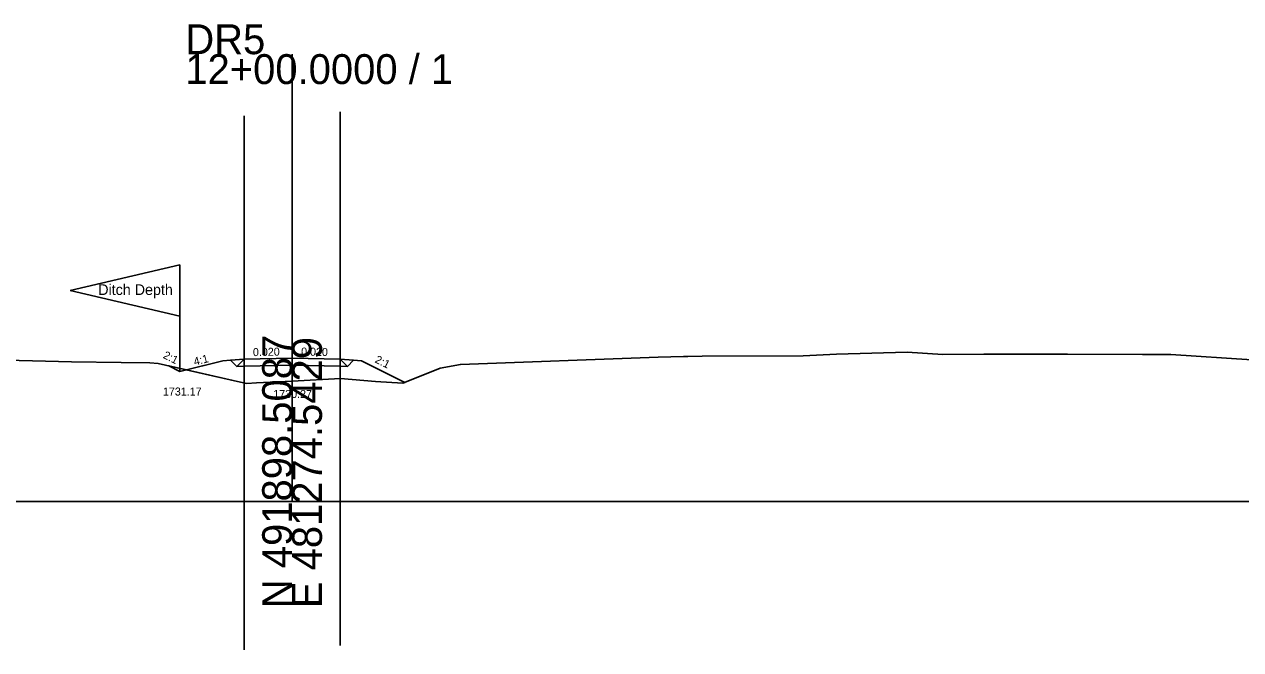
# Model space of a CAD drawing. Extents: x -26 to 403, y -10 to 2534.
# Drawn here: x 174.9 to 288.9, y 1986.1 to 2044.7 of the extents above; entities that cross this region are included whole.
import ezdxf

# ---------------------------------------------------------------- set-up
doc = ezdxf.new("R2010")
doc.units = 0
for name, color, linetype in [('Exist Cross Section Cell', 7, 'Continuous'), ('Exist XS Center Line Elevation Label', 7, 'Continuous'), ('Exist XS Ground Line', 7, 'Continuous'), ('Prop Road Sect_ Boring - Material (Outline)', 7, 'Continuous'), ('Prop XS Ditch Slope Text', 7, 'Continuous'), ('Prop XS Ditch Standard Text', 7, 'Continuous'), ('Prop XS Dump Level', 7, 'Continuous'), ('Prop XS Earthwork Shape', 7, 'Continuous'), ('Prop XS EOT Tick Mark', 7, 'Continuous'), ('Prop XS Finish Grade', 7, 'Continuous'), ('Prop XS Finish Grade Earthwork', 7, 'Continuous'), ('Prop XS Finish Grade Pavement', 7, 'Continuous'), ('Prop XS Hydro Typical Ditch Data', 7, 'Continuous'), ('Prop XS Pvmt Edge Slope', 7, 'Continuous'), ('Prop XS SE Text', 7, 'Continuous'), ('Prop XS Side Slope Text', 7, 'Continuous'), ('Prop XS Subgrade Earthwork', 7, 'Continuous'), ('Scratch_Level_4', 7, 'Continuous'), ('Scratch_Level_5', 7, 'Continuous')]:
    doc.layers.add(name, color=color, linetype=linetype)

msp = doc.modelspace()

# ---------------------------------------------------------------- linework, layer by layer
at = {"layer": 'Exist Cross Section Cell'}
for p, q in [((200, 2000), (200, 2041.9)), ((0, 2000), (200, 2000)), ((200, 2000), (400, 2000))]:
    msp.add_line(p, q, dxfattribs=at)
at = {"layer": 'Exist XS Ground Line'}
msp.add_lwpolyline([(170.74, 2013.29), (179.32, 2013.09), (184, 2013.01), (186.66, 2012.98), (187.45, 2012.92), (194.9, 2011.22), (195.77, 2011.06), (196.67, 2011.1), (200, 2011.27), (204.54, 2011.51), (207.83, 2011.25), (210.39, 2011.07), (213.88, 2012.47), (215.78, 2012.84), (234.31, 2013.52), (236.68, 2013.57), (237.07, 2013.57), (238.42, 2013.61), (247.89, 2013.65), (251.02, 2013.8), (257.63, 2013.97), (260.98, 2013.77), (264.81, 2013.8), (272.64, 2013.81), (279.67, 2013.76), (282.33, 2013.76), (289.93, 2013.26)], dxfattribs=at)
at = {"layer": 'Prop Road Sect_ Boring - Material (Outline)'}
for points in [[(195.5, 2013.33), (194.24, 2013.23), (194.82, 2012.65)], [(204.5, 2013.33), (205.76, 2013.23), (205.18, 2012.65)]]:
    msp.add_lwpolyline(points, close=True, dxfattribs=at)
at = {"layer": 'Prop XS Dump Level'}
for p, q in [((189.5, 2022.17), (179.2, 2019.77)), ((189.5, 2017.37), (189.5, 2022.17)), ((179.2, 2019.77), (189.5, 2017.37)), ((189.5, 2012.17), (189.5, 2017.37)), ((195.5, 2013.33), (200, 2013.42)), ((200, 2013.42), (204.5, 2013.33))]:
    msp.add_line(p, q, dxfattribs=at)
at = {"layer": 'Prop XS Earthwork Shape'}
for points in [[(189.5, 2012.17), (188.44, 2012.7), (190.1, 2012.32)], [(189.5, 2012.17), (188.44, 2012.7), (190.1, 2012.32)], [(189.5, 2012.17), (188.44, 2012.7), (190.1, 2012.32)], [(189.5, 2012.17), (188.44, 2012.7), (190.1, 2012.32)], [(194.82, 2012.65), (194.24, 2013.23), (193.5, 2013.17), (190.1, 2012.32), (194.9, 2011.22), (195.77, 2011.06), (196.67, 2011.1), (200, 2011.27), (204.54, 2011.51), (207.83, 2011.25), (210.39, 2011.07), (210.56, 2011.14), (206.5, 2013.17), (205.76, 2013.23), (205.18, 2012.65), (204.5, 2012.66), (200, 2012.75), (195.5, 2012.66)], [(194.82, 2012.65), (194.24, 2013.23), (193.5, 2013.17), (190.1, 2012.32), (194.9, 2011.22), (195.77, 2011.06), (196.67, 2011.1), (200, 2011.27), (204.54, 2011.51), (207.83, 2011.25), (210.39, 2011.07), (210.56, 2011.14), (206.5, 2013.17), (205.76, 2013.23), (205.18, 2012.65), (204.5, 2012.66), (200, 2012.75), (195.5, 2012.66)], [(194.9, 2011.22), (195.77, 2011.06), (196.67, 2011.1), (200, 2011.27), (204.54, 2011.51), (207.83, 2011.25), (210.39, 2011.07), (210.56, 2011.14), (206.5, 2013.17), (205.76, 2013.23), (205.18, 2012.65), (204.5, 2012.66), (200, 2012.75), (195.5, 2012.66), (194.82, 2012.65), (194.24, 2013.23), (193.5, 2013.17), (190.1, 2012.32)], [(194.82, 2012.65), (194.24, 2013.23), (193.5, 2013.17), (190.1, 2012.32), (194.9, 2011.22), (195.77, 2011.06), (196.67, 2011.1), (200, 2011.27), (204.54, 2011.51), (207.83, 2011.25), (210.39, 2011.07), (210.56, 2011.14), (206.5, 2013.17), (205.76, 2013.23), (205.18, 2012.65), (204.5, 2012.66), (200, 2012.75), (195.5, 2012.66)]]:
    msp.add_lwpolyline(points, close=True, dxfattribs=at)
at = {"layer": 'Prop XS EOT Tick Mark'}
for p, q in [((195.5, 2013.33), (195.5, 2014.33)), ((204.5, 2013.33), (204.5, 2014.33))]:
    msp.add_line(p, q, dxfattribs=at)
at = {"layer": 'Prop XS Finish Grade'}
for p, q in [((195.5, 2013.33), (194.24, 2013.23)), ((204.5, 2013.33), (205.76, 2013.23))]:
    msp.add_line(p, q, dxfattribs=at)
at = {"layer": 'Prop XS Finish Grade Earthwork'}
for p, q in [((189.5, 2012.17), (188.44, 2012.7)), ((193.5, 2013.17), (189.5, 2012.17)), ((194.24, 2013.23), (193.5, 2013.17)), ((205.76, 2013.23), (206.5, 2013.17)), ((206.5, 2013.17), (210.56, 2011.14))]:
    msp.add_line(p, q, dxfattribs=at)
at = {"layer": 'Prop XS Finish Grade Pavement'}
for p, q in [((195.5, 2013.33), (200, 2013.42)), ((200, 2013.42), (204.5, 2013.33))]:
    msp.add_line(p, q, dxfattribs=at)
at = {"layer": 'Prop XS Hydro Typical Ditch Data'}
for p, q in [((189.5, 2012.17), (188.44, 2012.7)), ((193.5, 2013.17), (189.5, 2012.17))]:
    msp.add_line(p, q, dxfattribs=at)
at = {"layer": 'Prop XS Pvmt Edge Slope'}
for p, q in [((195.5, 2013.33), (194.82, 2012.65)), ((204.5, 2013.33), (205.18, 2012.65))]:
    msp.add_line(p, q, dxfattribs=at)
at = {"layer": 'Prop XS Subgrade Earthwork'}
for p, q in [((194.82, 2012.65), (194.24, 2013.23)), ((195.5, 2012.66), (194.82, 2012.65)), ((200, 2012.75), (195.5, 2012.66)), ((204.5, 2012.66), (200, 2012.75)), ((204.5, 2012.66), (205.18, 2012.65)), ((205.18, 2012.65), (205.76, 2013.23))]:
    msp.add_line(p, q, dxfattribs=at)
at = {"layer": 'Scratch_Level_4'}
for p, q in [((195.5, 2036.11), (195.5, 1986.11)), ((204.5, 2036.51), (204.5, 1986.51))]:
    msp.add_line(p, q, dxfattribs=at)
at = {"layer": 'Scratch_Level_5'}
msp.add_lwpolyline([(170.74, 2013.29), (179.32, 2013.09), (184, 2013.01), (186.66, 2012.98), (187.45, 2012.92), (194.9, 2011.22), (195.77, 2011.06), (196.67, 2011.1), (200, 2011.27), (204.54, 2011.51), (207.83, 2011.25), (210.39, 2011.07), (213.88, 2012.47), (215.78, 2012.84), (234.31, 2013.52), (236.68, 2013.57), (237.07, 2013.57), (238.42, 2013.61), (247.89, 2013.65), (251.02, 2013.8), (257.63, 2013.97), (260.98, 2013.77), (264.81, 2013.8), (272.64, 2013.81), (279.67, 2013.76), (282.33, 2013.76), (289.93, 2013.26)], dxfattribs=at)

# ---------------------------------------------------------------- texts
at = {"layer": 'Exist Cross Section Cell'}
for s, p in [('DR5', (190, 2041.9)), ('12+00.0000 / 1', (190, 2039.1))]:
    msp.add_text(s, height=2.8, dxfattribs=at).set_placement(p)
for s, p in [('N 491898.5087', (200, 1990)), ('E 481274.5429', (202.8, 1990))]:
    msp.add_text(s, height=2.8, rotation=90, dxfattribs=at).set_placement(p)
at = {"layer": 'Exist XS Center Line Elevation Label'}
msp.add_text('1730.27', height=0.75, dxfattribs=at).set_placement((198.24, 2009.69))
at = {"layer": 'Prop XS Ditch Slope Text'}
msp.add_text('4:1', height=0.75, rotation=14.0362, dxfattribs=at).set_placement((190.88, 2012.72))
at = {"layer": 'Prop XS Ditch Standard Text'}
msp.add_text('1731.17', height=0.75, dxfattribs=at).set_placement((187.9, 2009.92))
at = {"layer": 'Prop XS Dump Level'}
for s, height, p in [('Ditch Depth', 1, (181.84, 2019.34)), ('Case1', 0.04, (193.5, 2013.13)), ('Case1', 0.04, (206.5, 2013.13))]:
    msp.add_text(s, height=height, dxfattribs=at).set_placement(p)
at = {"layer": 'Prop XS SE Text'}
for rotation, p in [(1.1458, (196.34, 2013.61)), (358.8542, (200.84, 2013.67))]:
    msp.add_text('0.020', height=0.75, rotation=rotation, dxfattribs=at).set_placement(p)
at = {"layer": 'Prop XS Side Slope Text'}
for p in [(187.85, 2013.46), (207.69, 2013.05)]:
    msp.add_text('2:1', height=0.75, rotation=333.4349, dxfattribs=at).set_placement(p)

doc.saveas('drawing.dxf')
